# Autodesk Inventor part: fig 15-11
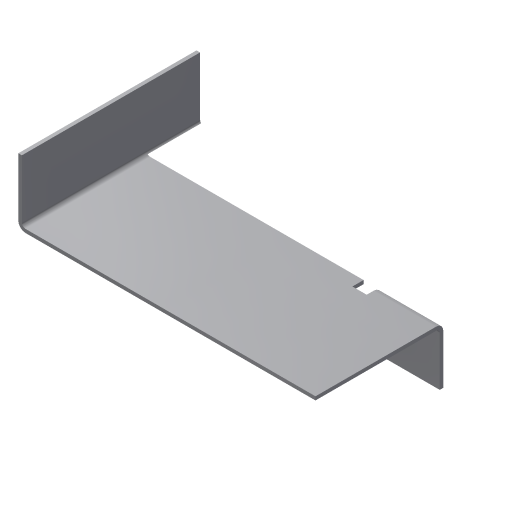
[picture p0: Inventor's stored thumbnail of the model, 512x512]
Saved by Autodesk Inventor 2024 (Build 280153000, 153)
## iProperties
Shininess: 77.0
Angle Display Precision: 2
Document Length Units: 11269
Document Angle Units: 11279
Document Time Units: 11290
Document Mass Units: 11283
Document Length Units Precision: 3
Document Angle Units Precision: 2
Created: 2002-04
Part Number: fig 15-11
Material: Aluminum-6061
Document SubType Name: Sheet Metal
Density: 1 g/cm^3
Sheet Metal Rule: Default
Appearance: Aluminum - Flat-1
Density: 0.0
Volumn: 0.0
Area: 0.0
PropertySet Name: Model Information
Control State: 0
Master: False
Checked Out: False
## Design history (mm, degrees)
node "Face1"
  sketch "Sketch1"
    geometry: L1 (-49.559, 19.574)-(-49.559, -30.426); L2 (-49.559, -30.426)-(50.441, -30.426); L3 (50.441, -30.426)-(50.441, 19.574); L4 (50.441, 19.574)-(32.941, 19.574); L5 (32.941, 19.574)-(32.941, 4.574); L6 (32.941, 4.574)-(-32.059, 4.574); L7 (-32.059, 4.574)-(-32.059, 19.574); L8 (-32.059, 19.574)-(-49.559, 19.574)
    constraints: 16 end point, 6 parallel, 2 equal length, 1 perpendicular, 1 vertical
    dimensions: "d0" = 100 distance of L1.end L2.end; "d1" = 65 distance of L5.end L6.end; "d2" = 15 distance of L6.end L7.end; "d3" = 50 distance of L1.start L1.end
feature "Fold2" dims "d8" = 1 (= BendRadius), "d9" = 90 deg, "d10" = 1 (= BendRadius), "d14" = 1 (= BendReliefWidth), "d15" = 0.5 (= BendReliefDepth), "d16" = 2 (= MinimumRemnant), "d20" = 1 (= Thickness), "SeamGap" = 0.01
feature "Fold3" dims "d11" = 1 (= BendRadius), "d12" = 90 deg, "d13" = 1 (= BendRadius), "d17" = 4, "d18" = 2, "d19" = 2 (= MinimumRemnant), "d20" = 1 (= Thickness), "SeamGap" = 0.01
body "Solid1"
sketch "Sketch2"
  geometry: L1 (100, 0)-(0, 0) reference; L2 (17.5, 50)-(17.5, 35) reference; L3 (82.5, 50)-(82.5, 0)
  constraints: 2 end point, 1 parallel, 1 point on line
face "Plate1" dims "d20" = 1 (= Thickness)
sketch "Sketch3"
  geometry: L1 (81.369, -50)-(0, -50) reference; L2 (17.5, 0)-(17.5, -50)
  constraints: 2 end point, 1 perpendicular, 1 point on line
sketch "Sketch4"
  geometry: L1 (17.5, 0)-(17.5, -50) reference; L2 (-63.869, -15)-(0, -15) reference; L3 (0, -15)-(17.5, -15)
  constraints: 2 end point, 1 collinear, 1 point on line
other parameters: "Thickness" = 1, "BendRadius" = 1 (= Thickness), "BendReliefWidth" = 1 (= Thickness), "BendReliefDepth" = 0.5 (= 0.5 x Thickness), "CornerReliefSize" = 4 (= 4 x Thickness), "MinimumRemnant" = 2 (= 2 x Thickness), "TransitionRadius" = 1 (= BendRadius), "d4" = 1 (= BendRadius), "JacobiRadiusSize" = 1 (= Thickness), "GapSize" = 1 (= Thickness)
